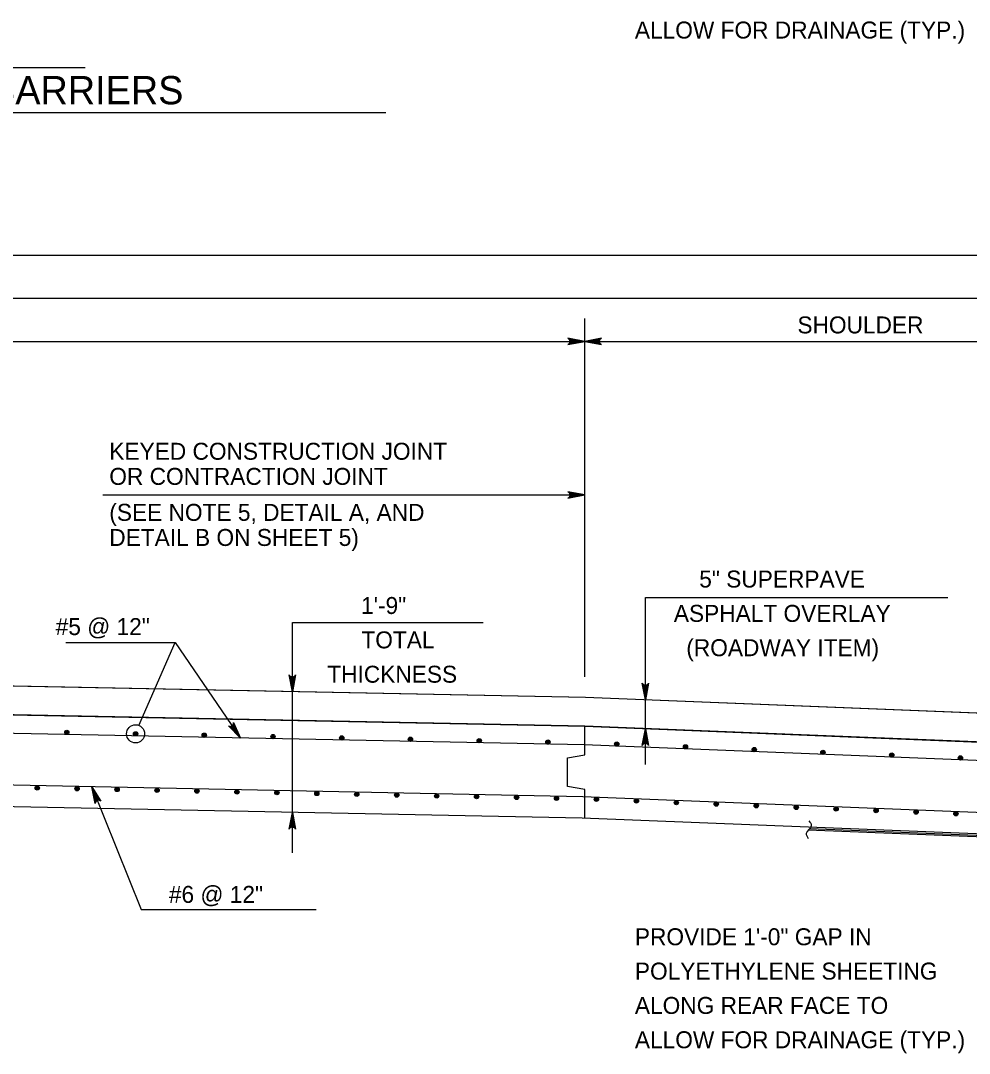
# Model space of a CAD drawing. Extents: x 636530 to 644067, y 294168 to 299122.
# Drawn here: x 638560.3 to 638728, y 297368.4 to 297551 of the extents above; entities that cross this region are included whole.
import ezdxf

# ---------------------------------------------------------------- set-up
doc = ezdxf.new("R2010")
doc.units = 0
doc.layers.add('1', color=7, linetype='Continuous')

msp = doc.modelspace()

# ---------------------------------------------------------------- linework, layer by layer
at = {"layer": '1'}
for p, q in [((638453.01, 297542.74), (638571.68, 297542.74)), ((638399.85, 297534.81), (638624.84, 297534.81)), ((638249.28, 297509.56), (638778.11, 297509.56)), ((638269.85, 297501.94), (638757.53, 297501.94)), ((638660, 297434.99), (638660, 297498.39)), ((638367.39, 297494.32), (638660, 297494.32)), ((638660, 297494.32), (638804.32, 297494.32)), ((638574.81, 297467.16), (638660, 297467.16)), ((638670.74, 297419.5), (638670.74, 297449.03)), ((638670.74, 297449.03), (638724.19, 297449.03)), ((638608.3, 297403.91), (638608.3, 297444.59)), ((638608.3, 297444.59), (638642.04, 297444.59)), ((638568.22, 297441.05), (638587.56, 297441.05)), ((638581.13, 297426.43), (638587.56, 297441.05)), ((638587.56, 297441.05), (638599.13, 297424.18)), ((638660.15, 297431.34), (638513.71, 297434.27)), ((638757.53, 297427.45), (638660.15, 297431.34)), ((638660, 297426.26), (638513.69, 297429.19)), ((638660, 297421.2), (638660, 297426.27)), ((638757.53, 297422.36), (638660, 297426.26)), ((638659.9, 297422.96), (638513.69, 297425.89)), ((638580.57, 297424.93), (638580.57, 297424.93)), ((638774.18, 297418.39), (638659.9, 297422.96)), ((638656.95, 297420.66), (638660, 297421.2)), ((638656.95, 297415.61), (638656.95, 297420.66)), ((638659.66, 297413.82), (638513.73, 297416.74)), ((638572.82, 297415.56), (638581.56, 297393.86)), ((638660, 297415.07), (638656.95, 297415.61)), ((638776.15, 297409.16), (638659.66, 297413.82)), ((638660, 297410.01), (638660, 297415.07)), ((638659.55, 297410.02), (638513.73, 297412.93)), ((638757.53, 297406.1), (638659.55, 297410.02)), ((638743.82, 297406.39), (638699.78, 297408.15)), ((638743.5, 297406.15), (638699.51, 297407.91)), ((638581.56, 297393.86), (638612.53, 297393.86))]:
    msp.add_line(p, q, dxfattribs=at)
for points in [[(638660, 297494.32), (638657.01, 297494.88), (638657.13, 297494.8), (638657.24, 297494.72), (638657.3, 297494.62), (638657.36, 297494.52), (638657.38, 297494.42), (638657.4, 297494.32), (638657.38, 297494.22), (638657.36, 297494.12), (638657.3, 297494.02), (638657.24, 297493.92), (638657.13, 297493.84), (638657.01, 297493.76), (638660, 297494.32), (638657.13, 297493.84), (638657.24, 297493.92), (638660, 297494.32), (638657.3, 297494.02), (638657.36, 297494.12), (638660, 297494.32), (638657.38, 297494.22), (638657.4, 297494.32), (638660, 297494.32), (638657.38, 297494.42), (638657.36, 297494.52), (638660, 297494.32), (638657.3, 297494.62), (638657.24, 297494.72), (638660, 297494.32), (638657.13, 297494.8)], [(638660, 297494.32), (638662.98, 297493.76), (638662.86, 297493.84), (638662.75, 297493.92), (638662.69, 297494.02), (638662.63, 297494.12), (638662.61, 297494.22), (638662.6, 297494.32), (638662.61, 297494.42), (638662.63, 297494.52), (638662.69, 297494.62), (638662.75, 297494.72), (638662.86, 297494.8), (638662.98, 297494.88), (638660, 297494.32), (638662.86, 297494.8), (638662.75, 297494.72), (638660, 297494.32), (638662.69, 297494.62), (638662.63, 297494.52), (638660, 297494.32), (638662.61, 297494.42), (638662.6, 297494.32), (638660, 297494.32), (638662.61, 297494.22), (638662.63, 297494.12), (638660, 297494.32), (638662.69, 297494.02), (638662.75, 297493.92), (638660, 297494.32), (638662.86, 297493.84)], [(638660, 297467.16), (638657.01, 297467.72), (638657.13, 297467.64), (638657.24, 297467.56), (638657.3, 297467.46), (638657.36, 297467.36), (638657.38, 297467.26), (638657.4, 297467.16), (638657.38, 297467.06), (638657.36, 297466.96), (638657.3, 297466.86), (638657.24, 297466.76), (638657.13, 297466.68), (638657.01, 297466.6), (638660, 297467.16), (638657.13, 297466.68), (638657.24, 297466.76), (638660, 297467.16), (638657.3, 297466.86), (638657.36, 297466.96), (638660, 297467.16), (638657.38, 297467.06), (638657.4, 297467.16), (638660, 297467.16), (638657.38, 297467.26), (638657.36, 297467.36), (638660, 297467.16), (638657.3, 297467.46), (638657.24, 297467.56), (638660, 297467.16), (638657.13, 297467.64)], [(638608.3, 297432.38), (638607.74, 297435.36), (638607.82, 297435.25), (638607.9, 297435.13), (638608, 297435.07), (638608.1, 297435.01), (638608.2, 297435), (638608.3, 297434.98), (638608.4, 297435), (638608.5, 297435.01), (638608.6, 297435.07), (638608.7, 297435.13), (638608.78, 297435.25), (638608.86, 297435.36), (638608.3, 297432.38), (638608.78, 297435.25), (638608.7, 297435.13), (638608.3, 297432.38), (638608.6, 297435.07), (638608.5, 297435.01), (638608.3, 297432.38), (638608.4, 297435), (638608.3, 297434.98), (638608.3, 297432.38), (638608.2, 297435), (638608.1, 297435.01), (638608.3, 297432.38), (638608, 297435.07), (638607.9, 297435.13), (638608.3, 297432.38), (638607.82, 297435.25)], [(638670.74, 297430.92), (638670.18, 297433.9), (638670.26, 297433.79), (638670.34, 297433.67), (638670.44, 297433.61), (638670.54, 297433.55), (638670.64, 297433.54), (638670.74, 297433.52), (638670.84, 297433.54), (638670.94, 297433.55), (638671.04, 297433.61), (638671.14, 297433.67), (638671.22, 297433.79), (638671.3, 297433.9), (638670.74, 297430.92), (638671.22, 297433.79), (638671.14, 297433.67), (638670.74, 297430.92), (638671.04, 297433.61), (638670.94, 297433.55), (638670.74, 297430.92), (638670.84, 297433.54), (638670.74, 297433.52), (638670.74, 297430.92), (638670.64, 297433.54), (638670.54, 297433.55), (638670.74, 297430.92), (638670.44, 297433.61), (638670.34, 297433.67), (638670.74, 297430.92), (638670.26, 297433.79)], [(638599.13, 297424.18), (638596.98, 297426.32), (638597.11, 297426.27), (638597.24, 297426.22), (638597.36, 297426.23), (638597.47, 297426.24), (638597.57, 297426.28), (638597.66, 297426.32), (638597.73, 297426.39), (638597.8, 297426.47), (638597.85, 297426.57), (638597.9, 297426.68), (638597.9, 297426.82), (638597.9, 297426.96), (638599.13, 297424.18), (638597.9, 297426.82), (638597.9, 297426.68), (638599.13, 297424.18), (638597.85, 297426.57), (638597.8, 297426.47), (638599.13, 297424.18), (638597.73, 297426.39), (638597.66, 297426.32), (638599.13, 297424.18), (638597.57, 297426.28), (638597.47, 297426.24), (638599.13, 297424.18), (638597.36, 297426.23), (638597.24, 297426.22), (638599.13, 297424.18), (638597.11, 297426.27)], [(638670.74, 297425.84), (638671.3, 297422.86), (638671.22, 297422.97), (638671.14, 297423.09), (638671.04, 297423.15), (638670.94, 297423.2), (638670.84, 297423.22), (638670.74, 297423.24), (638670.64, 297423.22), (638670.54, 297423.2), (638670.44, 297423.15), (638670.34, 297423.09), (638670.26, 297422.97), (638670.18, 297422.86), (638670.74, 297425.84), (638670.26, 297422.97), (638670.34, 297423.09), (638670.74, 297425.84), (638670.44, 297423.15), (638670.54, 297423.2), (638670.74, 297425.84), (638670.64, 297423.22), (638670.74, 297423.24), (638670.74, 297425.84), (638670.84, 297423.22), (638670.94, 297423.2), (638670.74, 297425.84), (638671.04, 297423.15), (638671.14, 297423.09), (638670.74, 297425.84), (638671.22, 297422.97)], [(638572.82, 297415.56), (638574.46, 297413), (638574.22, 297413.16), (638573.99, 297413.19), (638573.79, 297413.15), (638573.62, 297413.04), (638573.48, 297412.86), (638573.42, 297412.59), (638572.82, 297415.56), (638573.48, 297412.86), (638573.62, 297413.04), (638572.82, 297415.56), (638573.79, 297413.15), (638573.99, 297413.19), (638572.82, 297415.56), (638574.22, 297413.16)], [(638608.3, 297411.04), (638608.86, 297408.06), (638608.78, 297408.17), (638608.7, 297408.29), (638608.6, 297408.35), (638608.5, 297408.41), (638608.4, 297408.42), (638608.3, 297408.44), (638608.2, 297408.42), (638608.1, 297408.41), (638608, 297408.35), (638607.9, 297408.29), (638607.82, 297408.17), (638607.74, 297408.06), (638608.3, 297411.04), (638607.82, 297408.17), (638607.9, 297408.29), (638608.3, 297411.04), (638608, 297408.35), (638608.1, 297408.41), (638608.3, 297411.04), (638608.2, 297408.42), (638608.3, 297408.44), (638608.3, 297411.04), (638608.4, 297408.42), (638608.5, 297408.41), (638608.3, 297411.04), (638608.6, 297408.35), (638608.7, 297408.29), (638608.3, 297411.04), (638608.78, 297408.17)]]:
    msp.add_lwpolyline(points, dxfattribs=at)
msp.add_lwpolyline([(638269.85, 297422.37), (638367.39, 297426.26), (638513.69, 297429.19), (638660, 297426.26), (638757.53, 297422.36), (638757.53, 297427.45), (638660.15, 297431.34), (638513.68, 297434.27), (638367.24, 297431.34), (638269.85, 297427.45)], close=True, dxfattribs=at)
for centre, radius in [((638580.57, 297424.93), 1.6), ((638568.42, 297425.18), 0.381), ((638568.42, 297425.18), 0.286), ((638568.42, 297425.18), 0.19), ((638568.42, 297425.18), 0.0952), ((638580.57, 297424.93), 0.381), ((638580.57, 297424.93), 0.286), ((638580.57, 297424.93), 0.19), ((638580.57, 297424.93), 0.0952), ((638592.73, 297424.69), 0.381), ((638592.73, 297424.69), 0.286), ((638592.73, 297424.69), 0.19), ((638592.73, 297424.69), 0.0952), ((638604.88, 297424.45), 0.381), ((638604.88, 297424.45), 0.286), ((638604.88, 297424.45), 0.19), ((638604.88, 297424.45), 0.0952), ((638617.04, 297424.2), 0.381), ((638617.04, 297424.2), 0.286), ((638617.04, 297424.2), 0.19), ((638617.04, 297424.2), 0.0952), ((638629.19, 297423.96), 0.381), ((638629.19, 297423.96), 0.286), ((638629.19, 297423.96), 0.19), ((638629.19, 297423.96), 0.0952), ((638641.35, 297423.72), 0.381), ((638641.35, 297423.72), 0.286), ((638641.35, 297423.72), 0.19), ((638641.35, 297423.72), 0.0952), ((638653.5, 297423.47), 0.381), ((638653.5, 297423.47), 0.286), ((638653.5, 297423.47), 0.19), ((638653.5, 297423.47), 0.0952), ((638665.66, 297423.12), 0.381), ((638665.66, 297423.12), 0.286), ((638665.66, 297423.12), 0.19), ((638665.66, 297423.12), 0.0952), ((638677.82, 297422.63), 0.381), ((638677.82, 297422.63), 0.286), ((638677.82, 297422.63), 0.19), ((638677.82, 297422.63), 0.0952), ((638689.97, 297422.14), 0.381), ((638689.97, 297422.14), 0.286), ((638689.97, 297422.14), 0.19), ((638689.97, 297422.14), 0.0952), ((638702.13, 297421.66), 0.381), ((638702.13, 297421.66), 0.286), ((638702.13, 297421.66), 0.19), ((638702.13, 297421.66), 0.0952), ((638714.28, 297421.17), 0.381), ((638714.28, 297421.17), 0.286), ((638714.28, 297421.17), 0.19), ((638714.28, 297421.17), 0.0952), ((638726.44, 297420.68), 0.381), ((638726.44, 297420.68), 0.286), ((638726.44, 297420.68), 0.19), ((638726.44, 297420.68), 0.0952), ((638563.18, 297415.37), 0.381), ((638563.18, 297415.37), 0.286), ((638563.18, 297415.37), 0.19), ((638563.18, 297415.37), 0.0952), ((638570.24, 297415.23), 0.381), ((638570.24, 297415.23), 0.286), ((638570.24, 297415.23), 0.19), ((638570.24, 297415.23), 0.0952), ((638577.31, 297415.09), 0.381), ((638577.31, 297415.09), 0.286), ((638584.37, 297414.95), 0.381), ((638577.31, 297415.09), 0.19), ((638577.31, 297415.09), 0.0952), ((638584.37, 297414.95), 0.286), ((638584.37, 297414.95), 0.19), ((638584.37, 297414.95), 0.0952), ((638591.43, 297414.81), 0.381), ((638591.43, 297414.81), 0.286), ((638591.43, 297414.81), 0.19), ((638591.43, 297414.81), 0.0952), ((638598.5, 297414.67), 0.381), ((638598.5, 297414.67), 0.286), ((638598.5, 297414.67), 0.19), ((638598.5, 297414.67), 0.0952), ((638605.56, 297414.53), 0.381), ((638605.56, 297414.53), 0.286), ((638605.56, 297414.53), 0.19), ((638605.56, 297414.53), 0.0952), ((638612.63, 297414.38), 0.381), ((638612.63, 297414.38), 0.286), ((638612.63, 297414.38), 0.19), ((638612.63, 297414.38), 0.0952), ((638619.69, 297414.24), 0.381), ((638619.69, 297414.24), 0.286), ((638619.69, 297414.24), 0.19), ((638619.69, 297414.24), 0.0952), ((638626.75, 297414.1), 0.381), ((638626.75, 297414.1), 0.286), ((638626.75, 297414.1), 0.19), ((638626.75, 297414.1), 0.0952), ((638633.82, 297413.96), 0.381), ((638633.82, 297413.96), 0.286), ((638633.82, 297413.96), 0.19), ((638633.82, 297413.96), 0.0952), ((638640.88, 297413.82), 0.381), ((638640.88, 297413.82), 0.286), ((638640.88, 297413.82), 0.19), ((638640.88, 297413.82), 0.0952), ((638647.95, 297413.68), 0.381), ((638647.95, 297413.68), 0.286), ((638647.95, 297413.68), 0.19), ((638647.95, 297413.68), 0.0952), ((638655.01, 297413.54), 0.381), ((638655.01, 297413.54), 0.286), ((638655.01, 297413.54), 0.19), ((638655.01, 297413.54), 0.0952), ((638662.07, 297413.35), 0.381), ((638662.07, 297413.35), 0.286), ((638662.07, 297413.35), 0.19), ((638662.07, 297413.35), 0.0952), ((638669.14, 297413.06), 0.381), ((638669.14, 297413.06), 0.286), ((638669.14, 297413.06), 0.19), ((638669.14, 297413.06), 0.0952), ((638676.2, 297412.78), 0.381), ((638676.2, 297412.78), 0.286), ((638676.2, 297412.78), 0.19), ((638676.2, 297412.78), 0.0952), ((638683.27, 297412.5), 0.381), ((638683.27, 297412.5), 0.286), ((638683.27, 297412.5), 0.19), ((638683.27, 297412.5), 0.0952), ((638690.33, 297412.22), 0.381), ((638690.33, 297412.22), 0.286), ((638690.33, 297412.22), 0.19), ((638690.33, 297412.22), 0.0952), ((638697.4, 297411.93), 0.381), ((638697.4, 297411.93), 0.286), ((638697.4, 297411.93), 0.19), ((638697.4, 297411.93), 0.0952), ((638704.46, 297411.65), 0.381), ((638704.46, 297411.65), 0.286), ((638704.46, 297411.65), 0.19), ((638704.46, 297411.65), 0.0952), ((638711.52, 297411.37), 0.381), ((638711.52, 297411.37), 0.286), ((638711.52, 297411.37), 0.19), ((638711.52, 297411.37), 0.0952), ((638718.59, 297411.09), 0.381), ((638718.59, 297411.09), 0.286), ((638718.59, 297411.09), 0.19), ((638718.59, 297411.09), 0.0952), ((638725.65, 297410.8), 0.381), ((638725.65, 297410.8), 0.286), ((638725.65, 297410.8), 0.19), ((638725.65, 297410.8), 0.0952)]:
    msp.add_circle(centre, radius, dxfattribs=at)
msp.add_spline([(638699.64, 297409.56), (638700.07, 297408.68), (638699.15, 297407.32), (638699.53, 297406.45)], degree=3, dxfattribs=at)

# ---------------------------------------------------------------- texts
for s, height, p in [('ALLOW FOR DRAINAGE (TYP.)', 3, (638668.87, 297547.87)), ('CONCRETE APPROACH SLAB WITH ATTACHED BARRIERS', 5, (638400.31, 297536.24)), ('KEYED CONSTRUCTION JOINT', 3, (638575.93, 297473.39)), ('OR CONTRACTION JOINT', 3, (638575.93, 297468.95)), ('(SEE NOTE 5, DETAIL A, AND ', 3, (638575.93, 297462.59)), ('DETAIL B ON SHEET 5)', 3, (638575.93, 297458.15)), ('5" SUPERPAVE', 3, (638680.25, 297450.8)), ('1\'-9" ', 3, (638620.45, 297446.12)), ('ASPHALT OVERLAY', 3, (638675.76, 297444.73)), ('#5 @ 12"', 3, (638566.45, 297442.39)), ('TOTAL', 3, (638620.51, 297440.04)), ('(ROADWAY ITEM)', 3, (638677.96, 297438.66)), ('THICKNESS', 3, (638614.48, 297433.97)), ('#6 @ 12"', 3, (638586.47, 297395.04)), ('PROVIDE 1\'-0" GAP IN', 3, (638668.87, 297387.55)), ('POLYETHYLENE SHEETING', 3, (638668.87, 297381.48)), ('ALONG REAR FACE TO', 3, (638668.87, 297375.41)), ('ALLOW FOR DRAINAGE (TYP.)', 3, (638668.87, 297369.34))]:
    msp.add_text(s, height=height, dxfattribs=at).set_placement(p)
msp.add_text('SHOULDER', height=3, rotation=360, dxfattribs=at).set_placement((638697.61, 297495.73))

doc.saveas('drawing.dxf')
